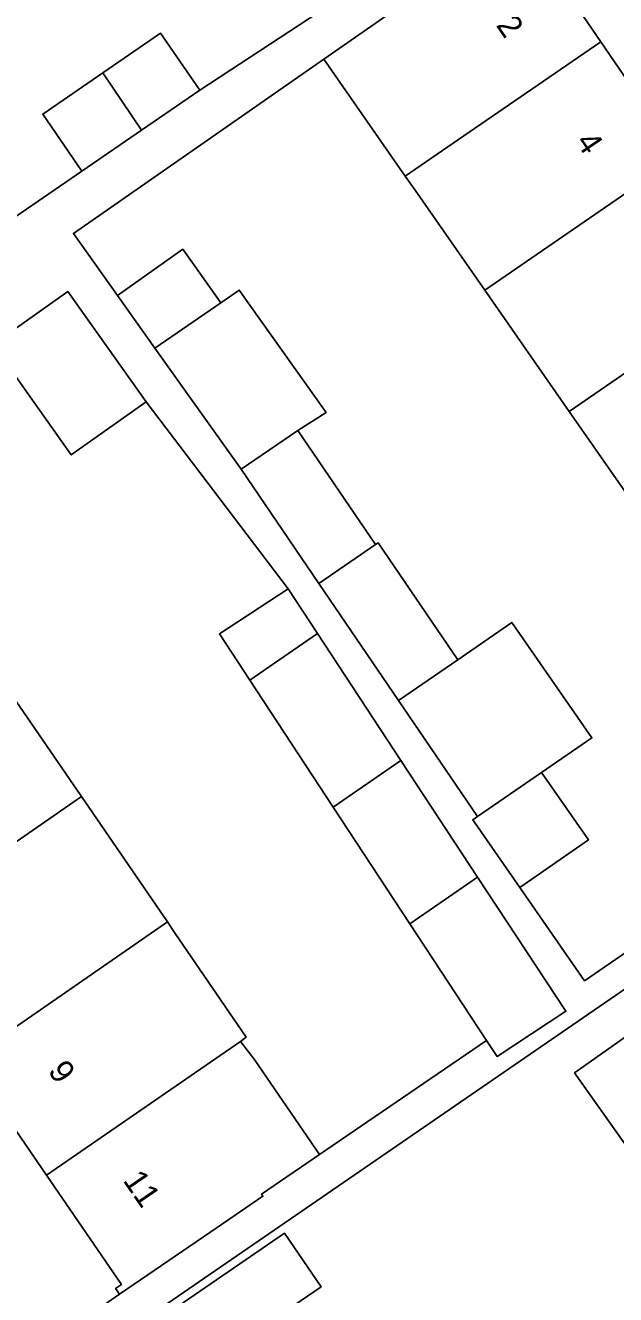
# Model space of a CAD drawing. Extents: x 157466 to 158888, y 383063 to 384677.
# Drawn here: x 158156.7 to 158181.7, y 383405.3 to 383459 of the extents above; entities that cross this region are included whole.
import ezdxf

# ---------------------------------------------------------------- set-up
doc = ezdxf.new("R2010")
doc.units = 0
for name, color, linetype in [('IMGEO_Pand', 7, 'Continuous'), ('IMGEO_Pand_nummerreeks', 7, 'Continuous'), ('IMGEO_Voetpad_open', 7, 'Continuous')]:
    doc.layers.add(name, color=color, linetype=linetype)

msp = doc.modelspace()

# ---------------------------------------------------------------- linework, layer by layer
at = {"layer": 'IMGEO_Pand'}
for points in [[(158169.354, 383457.528), (158171.846, 383459.264), (158173.774, 383460.608), (158177.876, 383463.466)], [(158177.876, 383463.466), (158178.045, 383463.218), (158177.797, 383463.048), (158181.061, 383458.265)], [(158160.017, 383456.947), (158162.458, 383458.625), (158164.113, 383456.218)], [(158172.798, 383452.583), (158175.495, 383454.438), (158181.061, 383458.265)], [(158181.061, 383458.265), (158184.374, 383453.411)], [(158172.798, 383452.583), (158169.354, 383457.528)], [(158159.135, 383452.796), (158157.48, 383455.202), (158160.017, 383456.947)], [(158161.658, 383454.53), (158160.017, 383456.947)], [(158164.113, 383456.218), (158161.658, 383454.53)], [(158161.658, 383454.53), (158159.135, 383452.796)], [(158184.374, 383453.411), (158176.157, 383447.762)], [(158176.157, 383447.762), (158173.217, 383451.982), (158172.798, 383452.583)], [(158160.638, 383447.533), (158163.392, 383449.49), (158165.002, 383447.223)], [(158187.898, 383448.248), (158179.731, 383442.632)], [(158155.371, 383445.461), (158158.536, 383447.706), (158161.848, 383443.037)], [(158168.262, 383441.815), (158169.453, 383442.587), (158165.78, 383447.758), (158165.002, 383447.223)], [(158179.731, 383442.632), (158176.157, 383447.762)], [(158162.218, 383445.309), (158160.638, 383447.533)], [(158165.002, 383447.223), (158162.218, 383445.309)], [(158161.848, 383443.037), (158158.682, 383440.792), (158155.371, 383445.461)], [(158162.218, 383445.309), (158165.861, 383440.182)], [(158183.156, 383437.715), (158179.731, 383442.632)], [(158165.861, 383440.182), (158168.262, 383441.815)], [(158171.538, 383436.998), (158168.262, 383441.815)], [(158165.861, 383440.182), (158169.145, 383435.353)], [(158171.538, 383436.998), (158169.145, 383435.353)], [(158175.02, 383432.12), (158171.65, 383437.075), (158171.538, 383436.998)], [(158169.145, 383435.353), (158172.514, 383430.398)], [(158166.23, 383431.258), (158164.942, 383433.219), (158167.851, 383435.129)], [(158167.851, 383435.129), (158169.093, 383433.239)], [(158169.093, 383433.239), (158166.23, 383431.258)], [(158169.093, 383433.239), (158172.618, 383427.87)], [(158178.562, 383427.356), (158180.691, 383428.82), (158177.308, 383433.694), (158175.02, 383432.12)], [(158172.514, 383430.398), (158175.02, 383432.12)], [(158155.848, 383431.113), (158159.117, 383426.337)], [(158169.755, 383425.889), (158166.23, 383431.258)], [(158172.514, 383430.398), (158175.85, 383425.491)], [(158169.755, 383425.889), (158172.618, 383427.87)], [(158172.618, 383427.87), (158175.859, 383422.935)], [(158175.85, 383425.491), (158178.562, 383427.356)], [(158177.643, 383422.493), (158180.541, 383424.505), (158178.562, 383427.356)], [(158150.669, 383420.492), (158159.117, 383426.337)], [(158159.117, 383426.337), (158162.744, 383421.038)], [(158172.996, 383420.954), (158169.755, 383425.889)], [(158175.85, 383425.491), (158175.655, 383425.357), (158177.643, 383422.493)], [(158175.859, 383422.935), (158172.996, 383420.954)], [(158176.235, 383416.023), (158176.679, 383415.346), (158179.589, 383417.256), (158175.859, 383422.935)], [(158162.744, 383421.038), (158154.298, 383415.194)], [(158162.744, 383421.038), (158163.049, 383420.592), (158166.076, 383416.165), (158165.838, 383415.982)], [(158172.996, 383420.954), (158176.235, 383416.023)], [(158185.913, 383410.953), (158183.685, 383409.381), (158179.959, 383414.659), (158182.253, 383416.279)], [(158157.635, 383410.324), (158165.838, 383415.982)], [(158165.838, 383415.982), (158166.411, 383415.237), (158169.177, 383411.193)], [(158157.635, 383410.324), (158154.298, 383415.194)], [(158169.177, 383411.193), (158166.725, 383409.515), (158166.782, 383409.432), (158164.851, 383408.111), (158160.724, 383405.287)], [(158160.724, 383405.287), (158160.554, 383405.534), (158160.801, 383405.703), (158157.635, 383410.324)], [(158162.928, 383404.605), (158164.479, 383402.339), (158169.249, 383405.603), (158167.698, 383407.869), (158162.928, 383404.605)]]:
    msp.add_lwpolyline(points, dxfattribs=at)
at = {"layer": 'IMGEO_Voetpad_open'}
for points in [[(158149.242, 383461.318), (158151.076, 383458.618), (158156.336, 383450.872), (158159.135, 383452.796)], [(158164.113, 383456.218), (158169.143, 383459.519)], [(158160.638, 383447.533), (158158.774, 383450.157), (158169.354, 383457.528)], [(158167.851, 383435.129), (158161.848, 383443.037)], [(158203.333, 383432.817), (158158.917, 383402.255)], [(158190.82, 383425.732), (158180.381, 383418.548), (158177.643, 383422.493)], [(158169.177, 383411.193), (158176.235, 383416.023)], [(158158.091, 383403.465), (158160.724, 383405.287)]]:
    msp.add_lwpolyline(points, dxfattribs=at)

# ---------------------------------------------------------------- texts
at = {"layer": 'IMGEO_Pand_nummerreeks'}
for s, rotation, p in [('2', 304.3132, (158176.614, 383458.964)), ('4', 304.3132, (158179.979, 383454.033)), ('9', 304.4167, (158157.669, 383414.734)), ('11', 304.4167, (158160.843, 383410.1))]:
    msp.add_text(s, height=1, rotation=rotation, dxfattribs=at).set_placement(p)

doc.saveas('drawing.dxf')
